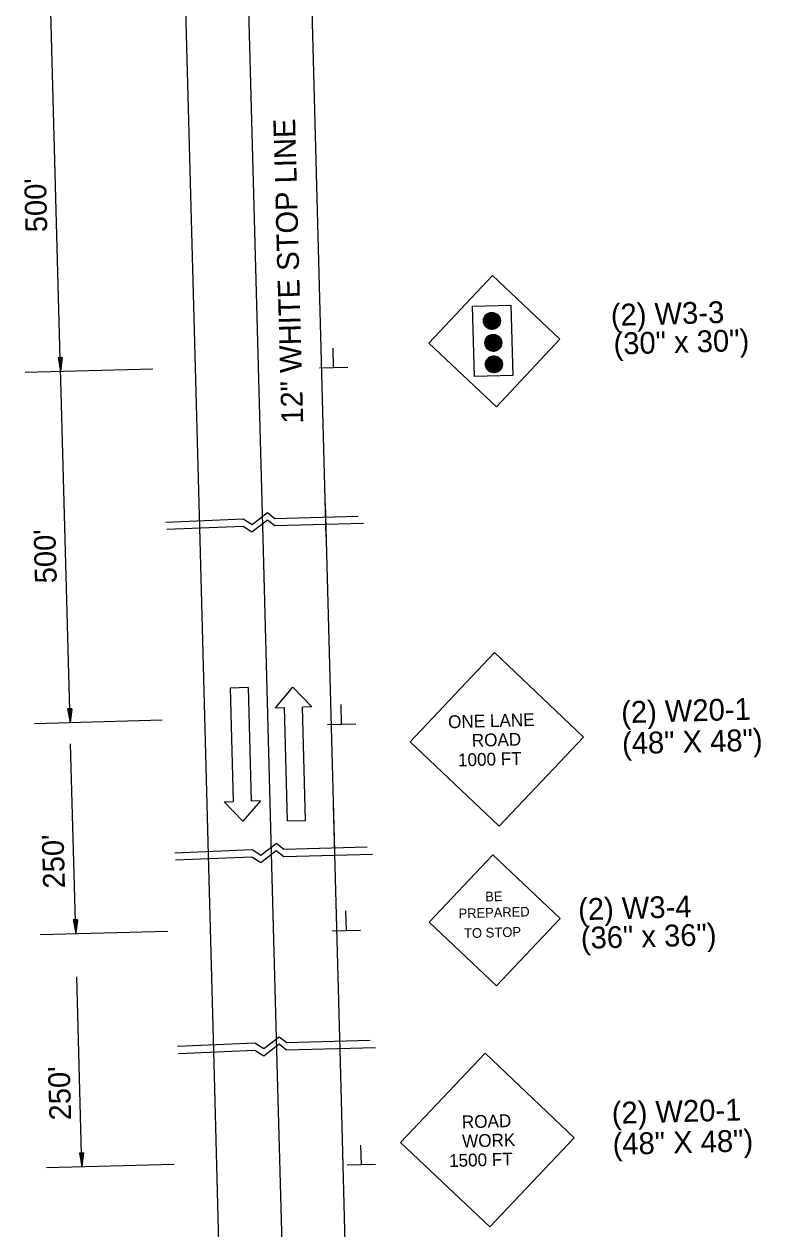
# Model space of a CAD drawing. Extents: x 1929624 to 1932070, y 596315 to 605533.
# Drawn here: x 1930893.3 to 1931096.1, y 596649.5 to 596981 of the extents above; entities that cross this region are included whole.
import ezdxf

# ---------------------------------------------------------------- set-up
doc = ezdxf.new("R2010")
doc.units = 0
doc.layers.add('Default', color=7, linetype='Continuous')
doc.layers.add('R_MOT', color=7, linetype='Continuous')

msp = doc.modelspace()

# ---------------------------------------------------------------- linework, layer by layer
at = {"layer": 'Default'}
for p, q in [((1930941.7, 596838.98), (1930937.4, 596998.85)), ((1930959.07, 596839.45), (1930954.78, 596999.31)), ((1930976.45, 596839.92), (1930972.16, 596999.78)), ((1930903.32, 596885.44), (1930900.67, 596984.24)), ((1931022.25, 596911.77), (1931004.73, 596893.23)), ((1931040.81, 596894.26), (1931022.25, 596911.77)), ((1931019.75, 596899.28), (1931021.98, 596901.64)), ((1931019.75, 596899.43), (1931021.83, 596901.63)), ((1931019.76, 596899.14), (1931022.12, 596901.64)), ((1931019.77, 596899.01), (1931022.26, 596901.63)), ((1931019.77, 596899.6), (1931021.67, 596901.6)), ((1931019.79, 596898.88), (1931022.38, 596901.62)), ((1931019.8, 596899.77), (1931021.5, 596901.57)), ((1931019.82, 596898.76), (1931022.5, 596901.6)), ((1931019.85, 596898.65), (1931022.62, 596901.58)), ((1931019.85, 596899.97), (1931021.3, 596901.51)), ((1931019.88, 596898.54), (1931022.73, 596901.55)), ((1931019.92, 596898.43), (1931022.84, 596901.51)), ((1931019.93, 596900.21), (1931021.07, 596901.41)), ((1931019.97, 596898.33), (1931022.94, 596901.47)), ((1931020.01, 596898.24), (1931023.04, 596901.43)), ((1931020.06, 596898.14), (1931023.14, 596901.39)), ((1931020.09, 596900.53), (1931020.76, 596901.23)), ((1931020.12, 596898.05), (1931023.23, 596901.34)), ((1931020.18, 596897.97), (1931023.32, 596901.28)), ((1931020.24, 596897.88), (1931023.4, 596901.23)), ((1931020.3, 596897.81), (1931023.49, 596901.17)), ((1931020.37, 596897.73), (1931023.57, 596901.1)), ((1931020.44, 596897.66), (1931023.64, 596901.04)), ((1931020.51, 596897.59), (1931023.72, 596900.97)), ((1931020.59, 596897.52), (1931023.79, 596900.89)), ((1931020.67, 596897.46), (1931023.85, 596900.82)), ((1931020.75, 596897.4), (1931023.92, 596900.74)), ((1931020.84, 596897.34), (1931023.98, 596900.66)), ((1931020.93, 596897.29), (1931024.04, 596900.57)), ((1931021.02, 596897.24), (1931024.09, 596900.48)), ((1931021.12, 596897.19), (1931024.14, 596900.39)), ((1931021.22, 596897.15), (1931024.19, 596900.29)), ((1931021.32, 596897.11), (1931024.24, 596900.19)), ((1931021.43, 596897.08), (1931024.28, 596900.08)), ((1931021.54, 596897.05), (1931024.31, 596899.97)), ((1931021.65, 596897.02), (1931024.34, 596899.86)), ((1931021.77, 596897), (1931024.37, 596899.74)), ((1931021.9, 596896.99), (1931024.39, 596899.61)), ((1931022.03, 596896.98), (1931024.4, 596899.48)), ((1931022.18, 596896.99), (1931024.41, 596899.34)), ((1931022.33, 596897), (1931024.4, 596899.19)), ((1931022.49, 596897.02), (1931024.39, 596899.03)), ((1931022.66, 596897.06), (1931024.36, 596898.85)), ((1931022.86, 596897.12), (1931024.31, 596898.65)), ((1931023.09, 596897.21), (1931024.23, 596898.41)), ((1931023.4, 596897.4), (1931024.06, 596898.09)), ((1931020.13, 596893.09), (1931022.5, 596895.59)), ((1931020.13, 596893.23), (1931022.36, 596895.58)), ((1931020.13, 596893.38), (1931022.21, 596895.57)), ((1931020.14, 596893.54), (1931022.05, 596895.55)), ((1931020.15, 596892.95), (1931022.63, 596895.58)), ((1931020.17, 596892.83), (1931022.76, 596895.57)), ((1931020.17, 596893.72), (1931021.87, 596895.51)), ((1931020.19, 596892.71), (1931022.88, 596895.55)), ((1931020.22, 596892.59), (1931023, 596895.52)), ((1931020.22, 596893.92), (1931021.67, 596895.45)), ((1931020.26, 596892.48), (1931023.11, 596895.49)), ((1931020.3, 596892.38), (1931023.22, 596895.46)), ((1931020.3, 596894.15), (1931021.44, 596895.35)), ((1931020.34, 596892.28), (1931023.32, 596895.42)), ((1931020.39, 596892.18), (1931023.42, 596895.38)), ((1931020.44, 596892.09), (1931023.51, 596895.33)), ((1931020.47, 596894.47), (1931021.13, 596895.18)), ((1931020.49, 596892), (1931023.61, 596895.28)), ((1931020.55, 596891.91), (1931023.69, 596895.23)), ((1931020.61, 596891.83), (1931023.78, 596895.17)), ((1931020.68, 596891.75), (1931023.86, 596895.11)), ((1931020.75, 596891.67), (1931023.94, 596895.05)), ((1931020.82, 596891.6), (1931024.02, 596894.98)), ((1931020.89, 596891.53), (1931024.09, 596894.91)), ((1931020.97, 596891.47), (1931024.16, 596894.84)), ((1931021.05, 596891.4), (1931024.23, 596894.76)), ((1931021.13, 596891.34), (1931024.29, 596894.68)), ((1931021.21, 596891.29), (1931024.36, 596894.6)), ((1931021.3, 596891.23), (1931024.41, 596894.51)), ((1931021.4, 596891.18), (1931024.47, 596894.42)), ((1930978.49, 596886.5), (1930978.35, 596891.84)), ((1931023.29, 596875.71), (1931004.73, 596893.23)), ((1931021.49, 596891.14), (1931024.52, 596894.33)), ((1931021.59, 596891.09), (1931024.57, 596894.23)), ((1931021.69, 596891.06), (1931024.61, 596894.13)), ((1931021.8, 596891.02), (1931024.65, 596894.03)), ((1931021.91, 596890.99), (1931024.69, 596893.92)), ((1931022.03, 596890.97), (1931024.72, 596893.8)), ((1931022.15, 596890.95), (1931024.74, 596893.68)), ((1931022.28, 596890.93), (1931024.76, 596893.56)), ((1931022.41, 596890.93), (1931024.78, 596893.43)), ((1931022.55, 596890.93), (1931024.78, 596893.28)), ((1931022.7, 596890.94), (1931024.78, 596893.13)), ((1931022.86, 596890.96), (1931024.77, 596892.97)), ((1931023.04, 596891), (1931024.74, 596892.79)), ((1931023.24, 596891.06), (1931024.69, 596892.59)), ((1931040.81, 596894.26), (1931023.29, 596875.71)), ((1931023.47, 596891.16), (1931024.6, 596892.36)), ((1931023.78, 596891.34), (1931024.44, 596892.04)), ((1930903.78, 596889.21), (1930902.65, 596889.18)), ((1930902.65, 596889.18), (1930903.32, 596885.44)), ((1930902.75, 596889.18), (1930903.3, 596886.07)), ((1930902.84, 596889.18), (1930903.28, 596886.71)), ((1930902.94, 596889.18), (1930903.27, 596887.34)), ((1930903.03, 596889.19), (1930903.25, 596887.97)), ((1930903.13, 596889.19), (1930903.23, 596888.6)), ((1930903.3, 596889.19), (1930903.23, 596888.6)), ((1930903.4, 596889.2), (1930903.25, 596887.97)), ((1930903.5, 596889.2), (1930903.27, 596887.34)), ((1930903.59, 596889.2), (1930903.28, 596886.71)), ((1930903.69, 596889.2), (1930903.3, 596886.07)), ((1930903.78, 596889.21), (1930903.32, 596885.44)), ((1931020.28, 596887.42), (1931022.43, 596889.69)), ((1931020.29, 596887.14), (1931022.72, 596889.7)), ((1931020.29, 596887.28), (1931022.58, 596889.7)), ((1931020.29, 596887.58), (1931022.28, 596889.67)), ((1931020.31, 596887.01), (1931022.85, 596889.69)), ((1931020.31, 596887.75), (1931022.11, 596889.64)), ((1931020.33, 596886.89), (1931022.97, 596889.67)), ((1931020.35, 596887.94), (1931021.92, 596889.59)), ((1931020.36, 596886.77), (1931023.09, 596889.65)), ((1931020.4, 596886.66), (1931023.2, 596889.62)), ((1931020.42, 596888.16), (1931021.71, 596889.52)), ((1931020.43, 596886.55), (1931023.31, 596889.59)), ((1931020.47, 596886.45), (1931023.42, 596889.55)), ((1931020.52, 596886.35), (1931023.52, 596889.51)), ((1931020.54, 596888.43), (1931021.45, 596889.39)), ((1931020.57, 596886.25), (1931023.62, 596889.47)), ((1931020.62, 596886.16), (1931023.71, 596889.42)), ((1931020.68, 596886.07), (1931023.8, 596889.37)), ((1931020.74, 596885.99), (1931023.89, 596889.32)), ((1931020.8, 596885.91), (1931023.98, 596889.26)), ((1931020.87, 596885.83), (1931024.06, 596889.2)), ((1931020.93, 596885.76), (1931024.13, 596889.13)), ((1931021.01, 596885.68), (1931024.21, 596889.06)), ((1931021.08, 596885.62), (1931024.28, 596888.99)), ((1931021.16, 596885.55), (1931024.35, 596888.92)), ((1931021.24, 596885.49), (1931024.42, 596888.84)), ((1931021.32, 596885.43), (1931024.48, 596888.76)), ((1931021.41, 596885.38), (1931024.54, 596888.68)), ((1931021.5, 596885.32), (1931024.6, 596888.59)), ((1931021.6, 596885.28), (1931024.65, 596888.5)), ((1931021.69, 596885.23), (1931024.7, 596888.4)), ((1931021.9, 596885.15), (1931024.79, 596888.2)), ((1931022.01, 596885.12), (1931024.83, 596888.09)), ((1931022.12, 596885.09), (1931024.86, 596887.98)), ((1931022.24, 596885.07), (1931024.89, 596887.87)), ((1931022.36, 596885.05), (1931024.91, 596887.74)), ((1930893.53, 596885.18), (1930928.73, 596886.13)), ((1930905.91, 596788.83), (1930903.29, 596886.28)), ((1930982.39, 596886.49), (1930974.56, 596886.28)), ((1931022.49, 596885.04), (1931024.93, 596887.61)), ((1931022.63, 596885.04), (1931024.94, 596887.48)), ((1931022.77, 596885.05), (1931024.94, 596887.33)), ((1931022.93, 596885.06), (1931024.93, 596887.18)), ((1931023.1, 596885.09), (1931024.91, 596887.01)), ((1931023.28, 596885.14), (1931024.88, 596886.82)), ((1931023.49, 596885.21), (1931024.81, 596886.61)), ((1931023.75, 596885.34), (1931024.7, 596886.35)), ((1931024.19, 596885.66), (1931024.41, 596885.89)), ((1930978.78, 596753.34), (1930976.21, 596849.09)), ((1930944.02, 596752.41), (1930941.7, 596838.98)), ((1930961.4, 596752.88), (1930959.07, 596839.45)), ((1931022.79, 596808.07), (1930999.53, 596783.53)), ((1931047.32, 596784.81), (1931022.79, 596808.07)), ((1930906.37, 596792.59), (1930905.25, 596792.56)), ((1930905.25, 596792.56), (1930905.91, 596788.83)), ((1930905.34, 596792.56), (1930905.89, 596789.45)), ((1930905.44, 596792.56), (1930905.88, 596790.1)), ((1930905.53, 596792.57), (1930905.86, 596790.72)), ((1930905.63, 596792.57), (1930905.84, 596791.36)), ((1930905.72, 596792.57), (1930905.83, 596791.98)), ((1930905.9, 596792.58), (1930905.83, 596791.98)), ((1930905.99, 596792.58), (1930905.84, 596791.36)), ((1930906.09, 596792.58), (1930905.86, 596790.72)), ((1930906.18, 596792.58), (1930905.88, 596790.1)), ((1930906.28, 596792.59), (1930905.89, 596789.45)), ((1930906.37, 596792.59), (1930905.91, 596788.83)), ((1930980.7, 596788.39), (1930980.56, 596793.72)), ((1930896.12, 596788.56), (1930931.32, 596789.51)), ((1930984.6, 596788.37), (1930976.78, 596788.16)), ((1930907.47, 596730.74), (1930906.07, 596782.91)), ((1931024.07, 596760.3), (1930999.53, 596783.53)), ((1931047.32, 596784.81), (1931024.07, 596760.3)), ((1930980.43, 596691.84), (1930978.43, 596766.16)), ((1930945.65, 596691.59), (1930944.02, 596752.41)), ((1930963.04, 596691.72), (1930961.4, 596752.88)), ((1931022.28, 596752.37), (1931004.76, 596733.83)), ((1931040.83, 596734.86), (1931022.28, 596752.37)), ((1930982.02, 596731.6), (1930981.88, 596736.94)), ((1930907.93, 596734.51), (1930906.81, 596734.48)), ((1930906.81, 596734.48), (1930907.47, 596730.74)), ((1930906.9, 596734.48), (1930907.45, 596731.37)), ((1930907, 596734.48), (1930907.44, 596732.02)), ((1930907.09, 596734.49), (1930907.42, 596732.64)), ((1930907.19, 596734.49), (1930907.4, 596733.28)), ((1930907.28, 596734.49), (1930907.39, 596733.9)), ((1930907.46, 596734.5), (1930907.39, 596733.9)), ((1930907.55, 596734.5), (1930907.4, 596733.28)), ((1930907.65, 596734.5), (1930907.42, 596732.64)), ((1930907.74, 596734.5), (1930907.44, 596732.02)), ((1930907.84, 596734.51), (1930907.45, 596731.37)), ((1930907.93, 596734.51), (1930907.47, 596730.74)), ((1931023.31, 596716.31), (1931004.76, 596733.83)), ((1931040.83, 596734.86), (1931023.31, 596716.31)), ((1930897.68, 596730.48), (1930932.88, 596731.43)), ((1930985.91, 596731.59), (1930978.09, 596731.38)), ((1930909.19, 596666.61), (1930907.79, 596718.78)), ((1931020.19, 596697.81), (1930996.94, 596673.27)), ((1931044.73, 596674.56), (1931020.19, 596697.81)), ((1930947.32, 596629.63), (1930945.65, 596691.59)), ((1930964.68, 596630.56), (1930963.04, 596691.72)), ((1930982.05, 596631.49), (1930980.43, 596691.84)), ((1930986.13, 596667.2), (1930985.99, 596672.54)), ((1931021.47, 596650.04), (1930996.94, 596673.27)), ((1931044.73, 596674.56), (1931021.47, 596650.04)), ((1930909.65, 596670.37), (1930908.53, 596670.34)), ((1930908.53, 596670.34), (1930909.19, 596666.61)), ((1930908.62, 596670.34), (1930909.18, 596667.23)), ((1930908.72, 596670.35), (1930909.16, 596667.88)), ((1930908.81, 596670.35), (1930909.14, 596668.5)), ((1930908.91, 596670.35), (1930909.12, 596669.14)), ((1930909, 596670.35), (1930909.11, 596669.76)), ((1930909.18, 596670.36), (1930909.11, 596669.76)), ((1930909.27, 596670.36), (1930909.12, 596669.14)), ((1930909.37, 596670.36), (1930909.14, 596668.5)), ((1930909.46, 596670.37), (1930909.16, 596667.88)), ((1930909.56, 596670.37), (1930909.18, 596667.23)), ((1930909.65, 596670.37), (1930909.19, 596666.61)), ((1930899.4, 596666.34), (1930934.6, 596667.29)), ((1930990.02, 596667.19), (1930982.2, 596666.98))]:
    msp.add_line(p, q, dxfattribs=at)
msp.add_lwpolyline([(1931016.76, 596903.41), (1931027.28, 596903.69), (1931027.8, 596884.28), (1931017.28, 596883.99)], close=True, dxfattribs=at)
for points in [[(1930932.29, 596843.97), (1930953.58, 596844.87), (1930956.04, 596843.31), (1930960.28, 596846.59), (1930962.33, 596844.98), (1930985.29, 596845.59)], [(1930932.54, 596841.98), (1930953.55, 596842.87), (1930956.01, 596841.31), (1930960.25, 596844.59), (1930962.3, 596842.98), (1930986.75, 596843.63)], [(1930934.74, 596752.96), (1930956.03, 596753.85), (1930958.49, 596752.29), (1930962.73, 596755.57), (1930964.77, 596753.96), (1930987.73, 596754.58)], [(1930934.98, 596750.97), (1930956, 596751.85), (1930958.46, 596750.3), (1930962.7, 596753.57), (1930964.74, 596751.96), (1930989.19, 596752.61)], [(1930935.53, 596699.74), (1930956.82, 596700.63), (1930959.28, 596699.07), (1930963.53, 596702.35), (1930965.57, 596700.74), (1930988.53, 596701.35)], [(1930935.78, 596697.75), (1930956.8, 596698.63), (1930959.25, 596697.07), (1930963.49, 596700.35), (1930965.54, 596698.74), (1930989.99, 596699.39)]]:
    msp.add_lwpolyline(points, dxfattribs=at)
for centre in [(1931022.08, 596899.31), (1931022.45, 596893.26), (1931022.61, 596887.37)]:
    msp.add_circle(centre, 2.33, dxfattribs=at)
at = {"layer": 'R_MOT'}
for p, q in [((1930954.97, 596798.42), (1930949.97, 596798.28)), ((1930949.97, 596798.28), (1930950.81, 596767.07)), ((1930954.97, 596798.42), (1930955.81, 596767.2)), ((1930962.45, 596792.87), (1930967.3, 596798.49)), ((1930967.3, 596798.49), (1930972.45, 596793.14)), ((1930962.45, 596792.87), (1930964.95, 596792.94)), ((1930965.79, 596761.73), (1930964.95, 596792.94)), ((1930972.45, 596793.14), (1930969.95, 596793.07)), ((1930970.79, 596761.86), (1930969.95, 596793.07)), ((1930948.31, 596767), (1930950.81, 596767.07)), ((1930953.46, 596761.65), (1930948.31, 596767)), ((1930958.31, 596767.27), (1930953.46, 596761.65)), ((1930958.31, 596767.27), (1930955.81, 596767.2)), ((1930965.79, 596761.73), (1930970.79, 596761.86))]:
    msp.add_line(p, q, dxfattribs=at)

# ---------------------------------------------------------------- texts
at = {"layer": 'Default'}
for s, height, rotation, p in [('12" WHITE STOP LINE', 6, 91.5377, (1930970.13, 596871.12)), ("500'", 6, 91.5377, (1930899.68, 596923.79)), ('(2) W3-3', 6, 1.5377, (1931054.89, 596897.93)), ('(30" x 30")', 6, 1.5377, (1931055.63, 596890.05)), ("500'", 6, 91.5377, (1930902.27, 596827.18)), ('(2) W20-1', 6, 1.5377, (1931057.74, 596788.61)), ('ONE LANE', 3.521, 1.5381, (1931010.05, 596787.22)), ('ROAD', 3.52, 1.5377, (1931016.57, 596782.11)), ('(48" X 48")', 6, 1.5377, (1931057.97, 596780.05)), ('1000 FT', 3.522, 1.5383, (1931012.77, 596776.72)), ("250'", 6, 91.5377, (1930904.53, 596743.2)), ('BE', 2.658, 1.6381, (1931020.27, 596739.54)), ('(2) W3-4', 6, 1.5377, (1931045.89, 596734.39)), ('PREPARED', 2.658, 1.638, (1931012.93, 596734.9)), ('TO STOP', 2.675, 1.5383, (1931014.43, 596729.46)), ('(36" x 36")', 6, 1.5377, (1931046.63, 596726.51)), ("250'", 6, 91.5377, (1930906.24, 596679.38)), ('(2) W20-1', 6, 1.5377, (1931055.15, 596678.35)), ('ROAD', 3.521, 1.5381, (1931013.84, 596677.13)), ('WORK', 3.52, 1.5377, (1931013.91, 596671.85)), ('(48" X 48")', 6, 1.5377, (1931055.38, 596669.79)), ('1500 FT', 3.522, 1.5383, (1931010.31, 596666.47))]:
    msp.add_text(s, height=height, rotation=rotation, dxfattribs=at).set_placement(p)

doc.saveas('drawing.dxf')
